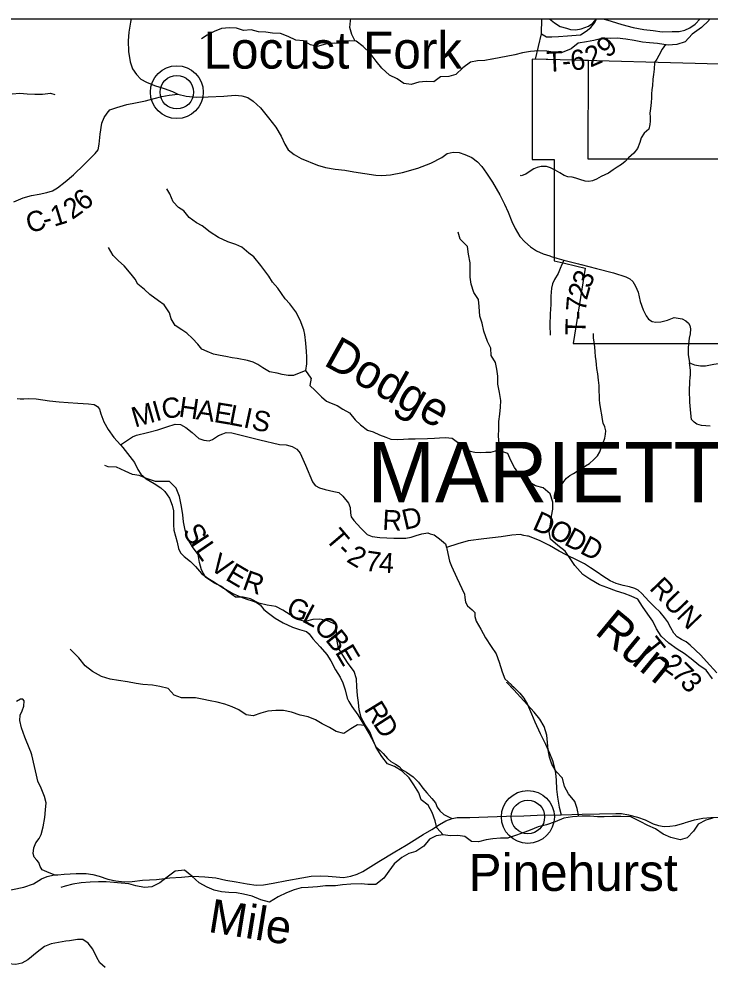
# Model space of a CAD drawing. Extents: x -84548 to 2262448, y -162180 to 525962.
# Drawn here: x 49199 to 59468, y 156808 to 170872 of the extents above; entities that cross this region are included whole.
import ezdxf

# ---------------------------------------------------------------- set-up
doc = ezdxf.new("R2010")
doc.units = 0
for name, color, linetype in [('GM_P_US_Location', 7, 'Continuous'), ('GM_X_Adjacent_County_Text', 7, 'Continuous'), ('GM_X_County', 7, 'Continuous'), ('GM_X_County_Road', 7, 'Continuous'), ('GM_X_Hydro', 7, 'Continuous'), ('GM_X_Major_Lake_Text', 7, 'Continuous'), ('GM_X_Major_River', 7, 'Continuous'), ('GM_X_Minor_Lake', 7, 'Continuous'), ('GM_X_Minor_River_Text', 7, 'Continuous'), ('GM_X_State_Route', 7, 'Continuous'), ('GM_X_Township_Road', 7, 'Continuous'), ('GM_X_Township_Road_Text', 7, 'Continuous'), ('GM_X_Township_Subdivision_Text', 7, 'Continuous'), ('GM_X_Unincorporated_Text', 7, 'Continuous')]:
    doc.layers.add(name, color=color, linetype=linetype)

msp = doc.modelspace()

# ---------------------------------------------------------------- linework, layer by layer
at = {"layer": 'GM_X_County'}
msp.add_line((31945, 170872), (67849, 170872), dxfattribs=at)
at = {"layer": 'GM_X_Hydro'}
for p, q in [((56961, 170650), (56966, 170872)), ((56872, 170274), (56961, 170650)), ((62492, 170126), (56872, 170274))]:
    msp.add_line(p, q, dxfattribs=at)
at = {"layer": 'GM_X_Major_Lake_Text'}
for points in [[(50867, 170872), (50855, 170824), (50830, 170674), (50823, 170547), (50829, 170387), (50850, 170235), (50887, 170131), (50944, 170046), (51012, 169976), (51093, 169931), (51215, 169882), (51355, 169839), (51480, 169794), (51562, 169756), (51684, 169723), (51830, 169711), (52012, 169716), (52244, 169724), (52410, 169738), (52510, 169731), (52600, 169705), (52681, 169650), (52788, 169549), (52909, 169402), (53014, 169264), (53093, 169131), (53149, 169009), (53201, 168927), (53288, 168858), (53392, 168799), (53633, 168701), (53755, 168666), (53900, 168637), (54042, 168622), (54174, 168601), (54500, 168550), (54592, 168543), (54720, 168554), (54898, 168589), (55125, 168656), (55319, 168727), (55484, 168813), (55563, 168870), (55649, 168891), (55741, 168885), (55824, 168856), (55928, 168813), (56012, 168749), (56079, 168680), (56148, 168578), (56233, 168445), (56345, 168259), (56413, 168121), (56466, 167999), (56523, 167860), (56570, 167756), (56643, 167640), (56716, 167557), (56799, 167483), (56891, 167424), (56990, 167382), (57088, 167350), (57108, 167343), (57192, 167318)], [(57192, 167318), (57294, 167287), (57515, 167232), (57549, 167223)], [(57549, 167223), (57550, 167223), (57780, 167162), (58031, 167096), (58217, 167039), (58275, 167010), (58322, 166968), (58360, 166900), (58397, 166812), (58428, 166674), (58473, 166547), (58516, 166461), (58552, 166407), (58605, 166375), (58661, 166364), (58735, 166372), (58835, 166397), (58936, 166432), (58994, 166426), (59053, 166415), (59109, 166387), (59147, 166351), (59167, 166316), (59178, 166264), (59170, 166189), (59159, 166127), (59158, 166124)], [(59158, 166124), (59151, 166085), (59140, 165983), (59143, 165885), (59164, 165761), (59234, 165733), (59326, 165718), (59400, 165716), (59522, 165739), (59742, 165769), (59964, 165813), (60208, 165859), (60267, 165874)], [(54950, 158592), (54951, 158593), (54992, 158617), (55203, 158749), (55334, 158826), (55447, 158898), (55543, 158951), (55636, 158987), (55710, 159000), (55740, 159000)], [(55740, 159000), (55742, 159000), (55898, 159002), (56168, 159010), (56441, 159020), (56699, 159028), (56901, 159035), (57255, 159042), (57568, 159051), (57824, 159057), (58066, 159062), (58152, 159059), (58254, 159042), (58389, 159005), (58503, 158966), (58624, 158910), (58700, 158885), (58786, 158870), (58870, 158872), (58954, 158885), (59080, 158920), (59105, 158927)], [(59105, 158927), (59137, 158937), (59236, 158967), (59361, 158992), (59477, 159003), (59640, 159006), (59770, 158999), (59918, 158988), (59986, 158982), (60132, 158968), (60193, 158962)], [(51766, 158129), (51785, 158130), (51963, 158118), (52123, 158103), (52275, 158072), (52427, 158044), (52588, 158015), (52724, 157998), (52832, 158001), (52974, 158027), (53181, 158064), (53403, 158106), (53543, 158128), (53674, 158133), (53794, 158130), (53911, 158119), (54019, 158112), (54130, 158129), (54222, 158158), (54310, 158198), (54546, 158347), (54783, 158493), (54950, 158592)], [(47344, 158036), (47348, 158036), (47517, 158028), (47663, 158031), (47761, 158047), (47800, 158065), (47879, 158100), (48016, 158179), (48120, 158218), (48205, 158224), (48306, 158195), (48408, 158152), (48520, 158084), (48669, 158003), (48803, 157950), (48943, 157923), (49103, 157930), (49274, 157965), (49416, 158014), (49494, 158066), (49537, 158091), (49621, 158127), (49723, 158148), (49776, 158152)], [(49776, 158152), (49776, 158152), (49871, 158158), (50051, 158169), (50200, 158171), (50295, 158155), (50391, 158132), (50519, 158087), (50637, 158062), (50764, 158047), (50883, 158052), (51033, 158068), (51241, 158081), (51439, 158103), (51615, 158117), (51766, 158129)]]:
    msp.add_lwpolyline(points, dxfattribs=at)
at = {"layer": 'GM_X_Major_River'}
for centre, radius in [((51545, 169783), 393), ((51545, 169783), 249), ((56761, 159010), 393), ((56761, 159010), 249)]:
    msp.add_circle(centre, radius, dxfattribs=at)
at = {"layer": 'GM_X_Minor_Lake'}
for points in [[(56961, 170650), (57037, 170606), (57119, 170605), (57215, 170609), (57347, 170620), (57542, 170635), (57629, 170689), (57696, 170744), (57757, 170818), (57780, 170872)], [(57083, 170872), (57155, 170813), (57240, 170762), (57333, 170734), (57396, 170716), (57473, 170708), (57552, 170727), (57660, 170766), (57724, 170811), (57780, 170872)], [(57880, 170872), (58000, 170839), (58159, 170790), (58326, 170744), (58483, 170715), (58624, 170698), (58756, 170683), (58904, 170684), (59008, 170684), (59094, 170704), (59169, 170739), (59244, 170793), (59321, 170872)], [(57294, 167287), (57256, 167197), (57251, 167185)], [(57251, 167185), (57210, 167090), (57156, 166997), (57125, 166936), (57111, 166871), (57103, 166753), (57100, 166627), (57091, 166488), (57089, 166320), (57090, 166170)], [(52230, 164706), (52277, 164724), (52363, 164721), (52523, 164681), (52777, 164616), (53071, 164546), (53169, 164542), (53259, 164518), (53329, 164479), (53378, 164419), (53457, 164241), (53562, 163993), (53602, 163937), (53666, 163901), (53748, 163879), (53880, 163850), (53950, 163832), (54013, 163776), (54095, 163673), (54118, 163611), (54126, 163527), (54136, 163473), (54176, 163419), (54281, 163305), (54375, 163207), (54448, 163181), (54560, 163164), (54768, 163153), (54949, 163154), (55025, 163168), (55101, 163192), (55183, 163219), (55275, 163231), (55311, 163221), (55311, 163220)], [(50741, 164500), (50811, 164411), (50914, 164279), (50966, 164173), (51011, 164106), (51089, 164038), (51207, 163968), (51308, 163901), (51368, 163847), (51434, 163751), (51477, 163645), (51495, 163561), (51494, 163453), (51494, 163352), (51503, 163274), (51527, 163186), (51548, 163096), (51570, 163000), (51600, 162936), (51655, 162882), (51749, 162805), (51825, 162733), (51912, 162631), (52004, 162561), (52106, 162498), (52241, 162411), (52241, 162411)], [(55311, 163220), (55367, 163204), (55449, 163144), (55538, 163068), (55553, 163013), (55558, 162994), (55597, 162810), (55625, 162738), (55704, 162566), (55821, 162324), (55826, 162270), (55836, 162202), (55866, 162146), (55934, 162090), (55971, 162048), (55971, 161990), (55993, 161922), (56060, 161800), (56132, 161674), (56215, 161545), (56288, 161433), (56334, 161311), (56379, 161165), (56419, 161065), (56517, 160972), (56518, 160971)], [(57422, 162863), (57421, 162864), (57329, 162908), (57225, 162963), (57080, 163043), (56932, 163121), (56769, 163184), (56753, 163186), (56753, 163186)], [(59570, 161154), (59414, 161323), (59332, 161416), (59171, 161564), (59110, 161611), (59043, 161648), (58978, 161689), (58929, 161742), (58887, 161821), (58837, 161916), (58793, 161977), (58726, 162052), (58640, 162132), (58558, 162219), (58454, 162330), (58399, 162379), (58350, 162408), (58271, 162429), (58177, 162451), (58070, 162479), (57981, 162521), (57874, 162587), (57792, 162651), (57693, 162715), (57602, 162771), (57454, 162848), (57422, 162863)], [(52241, 162411), (52267, 162394), (52379, 162331), (52491, 162283), (52583, 162247), (52678, 162220), (52728, 162200), (52782, 162162), (52840, 162096), (52906, 162037), (53005, 161965), (53127, 161897), (53263, 161832), (53367, 161798), (53470, 161767), (53512, 161733), (53568, 161657), (53675, 161539), (53773, 161427), (53834, 161329), (53902, 161196), (53971, 161088), (54013, 161002), (54044, 160902), (54076, 160778), (54099, 160728), (54145, 160652), (54234, 160526), (54322, 160380), (54403, 160244), (54476, 160106), (54500, 160050), (54564, 160000), (54612, 159955), (54675, 159881), (54723, 159835), (54793, 159797), (54847, 159761), (54889, 159717), (54958, 159674), (55056, 159604), (55136, 159526), (55199, 159440), (55259, 159369), (55335, 159285), (55390, 159219), (55414, 159155), (55454, 159099), (55511, 159045), (55589, 159009)], [(56518, 160971), (56555, 160936), (56639, 160852), (56700, 160777), (56757, 160680), (56816, 160541), (56866, 160424), (56944, 160253), (57023, 160093), (57082, 159960), (57125, 159848), (57151, 159755), (57171, 159661), (57179, 159559), (57184, 159423), (57201, 159303), (57228, 159157), (57255, 159042)], [(49376, 159980), (49376, 159980), (49363, 160013), (49288, 160197), (49239, 160337), (49213, 160443), (49216, 160523), (49246, 160587), (49270, 160658), (49275, 160738), (49255, 160762), (49221, 160760), (49165, 160727)], [(49723, 158148), (49615, 158193), (49544, 158225), (49516, 158273), (49494, 158333), (49466, 158369), (49427, 158413), (49413, 158469), (49421, 158553), (49450, 158625), (49502, 158691), (49530, 158750), (49561, 158862), (49582, 159004), (49596, 159117), (49605, 159221), (49579, 159313), (49528, 159439), (49481, 159543), (49461, 159631), (49430, 159759), (49393, 159933), (49376, 159980)], [(55589, 159009), (55636, 158987)], [(49950, 157171), (49896, 157163), (49676, 157123), (49578, 157083), (49471, 157000), (49332, 156885), (49242, 156835), (49154, 156819), (49040, 156828), (48868, 156847), (48762, 156879), (48636, 156932), (48455, 157008), (48347, 157033), (48237, 157077), (47993, 157178), (47925, 157238), (47896, 157312), (47888, 157420), (47872, 157680), (47800, 158065)], [(50479, 156774), (50401, 156840), (50357, 156922), (50298, 157046), (50230, 157132), (50150, 157186), (50070, 157189), (49950, 157171), (49950, 157171)]]:
    msp.add_lwpolyline(points, dxfattribs=at)
at = {"layer": 'GM_X_Minor_River_Text'}
for points in [[(49125, 168152), (49261, 168213), (49385, 168250), (49502, 168270), (49614, 168291), (49698, 168319), (49772, 168362), (49887, 168450), (50009, 168557), (50166, 168710), (50333, 168873), (50377, 168925), (50392, 169013), (50407, 169160), (50433, 169322), (50468, 169407), (50512, 169473), (50552, 169521), (50653, 169558), (50801, 169600), (50933, 169627), (51081, 169656), (51206, 169688), (51324, 169717), (51432, 169739), (51562, 169756)], [(59174, 165555), (59176, 165573), (59176, 165651), (59164, 165761)], [(59470, 164820), (59340, 164831), (59269, 164850), (59229, 164877), (59194, 164918), (59184, 165014), (59168, 165178), (59163, 165354), (59166, 165467), (59174, 165555)]]:
    msp.add_lwpolyline(points, dxfattribs=at)
at = {"layer": 'GM_X_State_Route'}
for points in [[(54196, 170541), (54146, 170642), (54114, 170746), (54126, 170846), (54131, 170872)], [(59461, 170872), (59448, 170851), (59338, 170743), (59200, 170644), (59096, 170530), (58972, 170494), (58844, 170480), (58688, 170506), (58570, 170518), (58466, 170526), (58342, 170552), (58216, 170570), (58088, 170586), (57986, 170582), (57880, 170584), (57742, 170554), (57634, 170530), (57508, 170514), (57404, 170428), (57270, 170371), (57164, 170375), (57044, 170392), (56918, 170400), (56798, 170390), (56680, 170367), (56569, 170339), (56232, 170273)], [(56232, 170273), (56227, 170275), (56123, 170253), (56014, 170249), (55909, 170231), (55793, 170145), (55688, 170044), (55586, 170016), (55463, 170014), (55362, 169936), (55248, 169944), (55141, 169934), (55029, 169900), (54920, 169912), (54818, 169982), (54705, 170034), (54591, 170139), (54508, 170245), (54420, 170363), (54313, 170461), (54209, 170540), (54108, 170548), (54008, 170509), (53885, 170511), (53752, 170499), (53630, 170465), (53529, 170487), (53429, 170548), (53312, 170556), (53198, 170612), (53083, 170654), (52966, 170662), (52866, 170674), (52757, 170682), (52651, 170708), (52536, 170700), (52432, 170734), (52327, 170738), (52209, 170730), (52098, 170686), (51995, 170632), (51911, 170576)], [(58803, 170491), (58755, 170424), (58705, 170331), (58678, 170275), (58641, 170224), (58637, 170128), (58629, 170044), (58618, 169976), (58610, 169880), (58602, 169824), (58599, 169752), (58598, 169701), (58592, 169629), (58582, 169539), (58573, 169471), (58576, 169413), (58576, 169353), (58571, 169303), (58560, 169235), (58486, 169176), (58445, 169107), (58423, 169035), (58389, 168944), (58336, 168877), (58258, 168808), (58207, 168755), (58152, 168710), (58085, 168670), (58026, 168631), (57959, 168578), (57903, 168555), (57848, 168531), (57779, 168492), (57722, 168465), (57666, 168456), (57612, 168460), (57535, 168487), (57473, 168505), (57421, 168518), (57355, 168523), (57300, 168547), (57237, 168584), (57165, 168624), (57096, 168657), (57038, 168677), (56960, 168677), (56900, 168666), (56849, 168645), (56780, 168598), (56730, 168567), (56663, 168541), (56649, 168543)], [(49097, 169760), (49213, 169770), (49324, 169760), (49436, 169752), (49547, 169752), (49667, 169768), (49734, 169750)], [(53540, 165532), (53460, 165647), (53479, 165744), (53479, 165848), (53472, 165928), (53463, 166053), (53447, 166183), (53432, 166253), (53378, 166395), (53313, 166517), (53225, 166638), (53154, 166713), (53046, 166869), (52965, 166960), (52911, 167051), (52793, 167206), (52687, 167338), (52617, 167393), (52513, 167482), (52421, 167521), (52302, 167557), (52163, 167625), (52038, 167704), (51922, 167795), (51838, 167840), (51730, 167923), (51649, 168020), (51570, 168069), (51493, 168154), (51440, 168272), (51399, 168346)], [(56391, 164439), (56336, 164560), (56325, 164672), (56329, 164778), (56331, 164890), (56344, 164995), (56355, 165099), (56358, 165199), (56337, 165321), (56314, 165442), (56312, 165560), (56299, 165666), (56279, 165766), (56215, 165869), (56209, 165977), (56161, 166079), (56108, 166233), (56082, 166350), (56049, 166452), (56035, 166596), (56027, 166703), (55959, 166807), (55917, 166929), (55901, 167033), (55905, 167136), (55905, 167246), (55881, 167378), (55863, 167490), (55754, 167597), (55726, 167701)], [(53540, 165532), (53460, 165647), (53278, 165570), (53200, 165573), (53108, 165586), (53036, 165607), (52921, 165629), (52824, 165684), (52751, 165735), (52677, 165768), (52594, 165793), (52442, 165827), (52365, 165836), (52275, 165855), (52187, 165868), (52092, 165889), (51998, 165930), (51915, 165965), (51858, 166040), (51779, 166123), (51694, 166203), (51621, 166250), (51518, 166313), (51459, 166416), (51435, 166506), (51356, 166622), (51273, 166683), (51146, 166777), (51063, 166848), (50965, 166931), (50924, 167005), (50867, 167079), (50762, 167200), (50681, 167275), (50601, 167358), (50528, 167476)], [(57157, 163740), (57156, 163792), (57173, 163852), (57212, 163915), (57280, 163978), (57335, 164047), (57386, 164086), (57439, 164117), (57494, 164148), (57554, 164179), (57619, 164227), (57674, 164266), (57741, 164323), (57797, 164376), (57832, 164437), (57849, 164497), (57877, 164571), (57902, 164640), (57916, 164698), (57917, 164750), (57902, 164807), (57881, 164865), (57868, 164916), (57858, 164986), (57845, 165065), (57831, 165161), (57826, 165212), (57823, 165262), (57821, 165350), (57819, 165424), (57811, 165505), (57798, 165597), (57784, 165678), (57779, 165736), (57773, 165790), (57764, 165853), (57761, 165923), (57757, 165997), (57747, 166072), (57738, 166128), (57737, 166188), (57737, 166194)], [(53540, 165532), (53521, 165425), (53598, 165348), (53693, 165254), (53768, 165193), (53838, 165162), (53929, 165125), (54012, 165072), (54109, 165019), (54194, 164912), (54275, 164839), (54378, 164760), (54463, 164735), (54558, 164692), (54652, 164655), (54723, 164626), (54825, 164620), (54913, 164625), (54987, 164630), (55085, 164633), (55270, 164636), (55372, 164641), (55450, 164645), (55538, 164650), (55634, 164639), (55715, 164580), (55784, 164491), (55903, 164448), (55973, 164431), (56054, 164426), (56136, 164431), (56210, 164434), (56282, 164453), (56391, 164439)], [(59503, 161064), (59409, 161190), (59301, 161264), (59187, 161360), (59081, 161441), (58979, 161505), (58853, 161591), (58743, 161695), (58671, 161808), (58615, 161918), (58541, 162022), (58465, 162139), (58395, 162245), (58293, 162291), (58189, 162331), (58077, 162365), (57933, 162420), (57823, 162460), (57681, 162546), (57575, 162614), (57457, 162746), (57391, 162853), (57313, 162963), (57207, 163043), (57097, 163140), (57079, 163250), (57095, 163364), (57113, 163483), (57131, 163587), (57131, 163687), (57093, 163814), (56987, 163900), (56875, 163930), (56757, 164002), (56649, 164082), (56564, 164203), (56506, 164311), (56462, 164411), (56391, 164439)], [(56455, 158696), (56352, 158694), (56242, 158686), (56139, 158670), (56029, 158640), (55923, 158646), (55822, 158720), (55720, 158734), (55605, 158728), (55501, 158746), (55406, 158846), (55382, 158952), (55340, 159075), (55279, 159183), (55173, 159263), (55141, 159367), (55068, 159488), (54996, 159590), (54893, 159690), (54781, 159758), (54676, 159800), (54590, 159911), (54507, 160043), (54459, 160163), (54415, 160277), (54341, 160378), (54282, 160490), (54252, 160600), (54242, 160710), (54230, 160813), (54218, 160943), (54214, 161063), (54182, 161174), (54081, 161304), (54011, 161414), (53947, 161520), (53922, 161653), (53918, 161757), (53906, 161869), (53784, 161927), (53671, 161951), (53567, 161947), (53452, 161913), (53335, 161947), (53231, 162015), (53122, 162086), (53014, 162136), (52889, 162160), (52762, 162186), (52642, 162250), (52533, 162278), (52417, 162276), (52310, 162356), (52208, 162436), (52095, 162490), (51970, 162573), (51910, 162683), (51884, 162793), (51862, 162913), (51777, 163026), (51707, 163144), (51669, 163272), (51643, 163399), (51633, 163501), (51615, 163623), (51584, 163773), (51536, 163896), (51436, 163998), (51331, 163998), (51229, 163994), (51110, 164036), (50987, 164088), (50885, 164102), (50780, 164152), (50648, 164208), (50527, 164212), (50475, 164234)], [(54346, 160370), (54230, 160378), (54128, 160322), (54025, 160249), (53914, 160279), (53814, 160342), (53705, 160394), (53605, 160452), (53494, 160496), (53378, 160524), (53251, 160566), (53128, 160594), (53018, 160594), (52895, 160584), (52793, 160552), (52680, 160512), (52576, 160526), (52465, 160604), (52365, 160648), (52260, 160688), (52143, 160716), (52041, 160736), (51924, 160762), (51824, 160779), (51719, 160781), (51617, 160783), (51508, 160819), (51416, 160921), (51295, 160951), (51186, 160967), (51042, 160977), (50939, 160995), (50811, 161021), (50680, 161039), (50555, 161057), (50427, 161099), (50294, 161173), (50181, 161256), (50087, 161374), (49976, 161490), (49960, 161502)], [(57517, 159018), (57493, 159138), (57457, 159240), (57363, 159354), (57305, 159463), (57275, 159585), (57179, 159687), (57115, 159796), (57081, 159900), (57061, 160010), (57051, 160119), (57043, 160225), (57005, 160355), (56939, 160462), (56853, 160568), (56755, 160678), (56649, 160791), (56551, 160901), (56449, 161011), (56449, 161013)], [(59509, 158991), (59407, 158961), (59293, 158901), (59219, 158799), (59125, 158699), (59021, 158668), (58887, 158703), (58773, 158755), (58655, 158831), (58543, 158881), (58429, 158941), (58289, 159013), (58143, 159015), (58017, 159017), (57895, 159013), (57793, 159013), (57687, 159021), (57569, 159021), (57423, 159011), (57293, 158991), (57165, 158939), (57039, 158895), (56915, 158865), (56794, 158815), (56676, 158769), (56560, 158728), (56458, 158694), (56458, 158692)], [(55501, 158746), (55400, 158730), (55300, 158678), (55213, 158574), (55097, 158497), (54992, 158465), (54888, 158409), (54775, 158311), (54697, 158203), (54622, 158098), (54502, 158004), (54385, 158006), (54282, 158016), (54130, 158012), (54009, 158000), (53905, 157988), (53756, 157984), (53635, 157972), (53496, 157962), (53394, 157956), (53289, 157928), (53175, 157880), (53050, 157824), (52922, 157744), (52795, 157780), (52664, 157832), (52538, 157860), (52431, 157882), (52320, 157886), (52210, 157898), (52099, 157924), (51997, 157966), (51876, 158030), (51768, 158128), (51659, 158217), (51522, 158205), (51400, 158116), (51291, 158030), (51173, 157970), (51066, 157960), (50937, 157984), (50831, 158014), (50720, 158024), (50610, 158036), (50497, 158048), (50379, 158048), (50260, 158042), (50125, 158030), (50001, 158010), (49888, 157982), (49822, 157962)]]:
    msp.add_lwpolyline(points, dxfattribs=at)
at = {"layer": 'GM_X_Township_Road_Text'}
for points in [[(49172, 165231), (49218, 165225), (49272, 165226), (49340, 165230), (49456, 165223), (49652, 165197), (49798, 165180), (49932, 165169), (50074, 165161), (50234, 165152), (50318, 165140), (50366, 165112), (50396, 165070), (50418, 165000), (50463, 164884), (50524, 164771), (50610, 164651), (50709, 164541), (50741, 164500), (50741, 164500)], [(50709, 164541), (50888, 164658), (50946, 164684), (51111, 164727), (51265, 164764), (51395, 164811), (51519, 164851), (51599, 164843), (51679, 164800), (51773, 164724), (51873, 164638), (51946, 164613), (52026, 164603), (52077, 164623), (52165, 164680), (52228, 164705), (52230, 164706)], [(56701, 163196), (56644, 163207), (56520, 163199), (56364, 163176), (56107, 163145), (55873, 163113), (55720, 163068), (55553, 163013)], [(56753, 163186), (56701, 163196)]]:
    msp.add_lwpolyline(points, dxfattribs=at)
at = {"layer": 'GM_X_Township_Subdivision_Text'}
msp.add_lwpolyline([(60976, 168788), (57658, 168788), (57659, 170253), (56823, 170275), (56823, 168784), (57153, 168784), (57152, 167277), (57284, 167246), (57490, 167197), (57611, 167169), (57433, 166050), (60133, 166050)], dxfattribs=at)

# ---------------------------------------------------------------- texts
at = {"layer": 'GM_P_US_Location'}
msp.add_text('MARIETTA', height=900, rotation=0, dxfattribs=at).set_placement((54378, 163686))
at = {"layer": 'GM_X_Adjacent_County_Text'}
for s, p in [('Locust Fork', (51941, 170134)), ('Pinehurst', (55879, 157911))]:
    msp.add_text(s, height=550, rotation=0, dxfattribs=at).set_placement(p)
at = {"layer": 'GM_X_County_Road'}
for s, rotation, p in [('6', 39.5945, (50161, 168003)), ('2', 35.2275, (49991, 167881)), ('1', 17.018, (49721, 167782)), ('C', 13.7674, (49344, 167688)), ('-', 14.1041, (49585, 167747))]:
    msp.add_text(s, height=300, rotation=rotation, dxfattribs=at).set_placement(p)
at = {"layer": 'GM_X_Township_Road'}
for s, rotation, p in [('9', 42.276, (57948, 170279)), ('2', 23.4365, (57689, 170147)), ('T', 2.6281, (57043, 170085)), ('6', 4.9715, (57403, 170106)), ('-', 4.3267, (57277, 170096)), ('3', 68.3445, (57682, 166853)), ('2', 74.5393, (57636, 166683)), ('7', 85.447, (57624, 166514)), ('T', 89.0485, (57617, 166171)), ('-', 88.3839, (57621, 166395)), ('M', 16.1198, (50922, 164797)), ('I', 15.8939, (51235, 164888)), ('C', 9.6445, (51345, 164920)), ('H', 351.6929, (51563, 164961)), ('A', 351.1365, (51823, 164923)), ('E', 350.6955, (52084, 164882)), ('L', 349.07, (52303, 164846)), ('I', 347.8458, (52521, 164804)), ('S', 347.5117, (52641, 164778)), ('R', 357.0481, (54594, 163279)), ('D', 13.0852, (54929, 163274)), ('D', 336.225, (56813, 163291)), ('S', 303.4331, (51621, 163250)), ('T', 310.3661, (53739, 163139)), ('O', 332.4232, (57050, 163187)), ('D', 332.0289, (57284, 163065)), ('I', 303.4542, (51733, 163081)), ('D', 332.5083, (57519, 162939)), ('L', 304.465, (51804, 162974)), ('-', 314.4953, (53900, 162951)), ('2', 329.1339, (54052, 162812)), ('V', 325.6014, (52016, 162704)), ('7', 351.9207, (54333, 162674)), ('4', 356.4574, (54541, 162645)), ('E', 329.4073, (52252, 162543)), ('R', 340.2827, (52502, 162402)), ('RUN', 313.919, (58552, 162399)), ('G', 337.9733, (53152, 162017)), ('L', 332.1622, (53390, 161922)), ('O', 311.9385, (53566, 161834)), ('B', 309.2084, (53740, 161641)), ('T', 308.7923, (58434, 161533)), ('E', 300.5566, (53889, 161459)), ('-', 323.0473, (58633, 161302)), ('2', 324.8337, (58740, 161221)), ('7', 314.7774, (58880, 161124)), ('3', 312.405, (59008, 160995)), ('R', 301.5712, (54319, 160612)), ('D', 302.9187, (54452, 160396))]:
    msp.add_text(s, height=300, rotation=rotation, dxfattribs=at).set_placement(p)
at = {"layer": 'GM_X_Unincorporated_Text'}
for s, rotation, p in [('Dodge', 330.8086, (53709, 165735)), ('Run', 320.4728, (57738, 161745)), ('Mile', 350.8123, (51996, 157303))]:
    msp.add_text(s, height=500, rotation=rotation, dxfattribs=at).set_placement(p)

doc.saveas('drawing.dxf')
